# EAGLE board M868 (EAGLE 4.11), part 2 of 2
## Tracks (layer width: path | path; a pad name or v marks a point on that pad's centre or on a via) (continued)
N$55 (continued)
  Bottom 0.254: D10.C 38.73,139.07 40.01,139.07 D9.C
N$56
  Top 0.254: D6.A 40.64,41.91 38.73,43.82 38.73,50.17 D4.C
N$57
  Top 0.254: Q5.1 40.64,120.02 38.1,122.56 D10.A
N$58
  Top 0.254: Q3.1 45.72,74.3 44.45,75.57 44.45,124.46 40.64,128.27 D9.A
N$59
  Top 0.254: Q2.1 38.1,74.3 39.37,75.57 39.37,120.02 36.83,122.56 36.83,130.81 36.2,131.45 33.02,131.45 D9A.A
N$60
  Top 0.254: Q4.1 30.48,120.02 31.75,121.29 31.75,124.46 35.56,128.27 D7.A
N$61
  Bottom 0.254: E24.11 148.59,43.18 150.5,41.28 153.03,41.28 W2W1.2
N$62
  Bottom 0.254: E24.12 148.59,45.72 150.5,43.82 151.76,43.82 W4W3.2
N$63
  Top 0.254: D9A.C R39.2
  Bottom 0.254: D9A.C 33.66,139.07 34.92,139.07 D7.C
N$65
  Bottom 0.254: E20.3 158.75,45.72 156.84,47.63 155.57,47.63 W2W1.3
N$66  (via drill 0.61)
  Top 0.254: v68.58,53.34 68.58,40.64 E40.8 | v124.46,54.61 128.27,58.42 v128.27,116.84 | v150.5,180.34 133.35,163.2 v133.35,119.38
  Bottom 0.254: v68.58,53.34 104.14,53.34 105.41,54.61 v124.46,54.61 | v128.27,116.84 130.81,119.38 v133.35,119.38 E26.1 | v150.5,180.34 177.8,180.34 179.07,181.61 185.42,181.61 186.69,182.88 E19.12
N$67
  Bottom 0.254: E20.2 158.75,48.26 156.84,50.17 154.31,50.17 W4W3.3
N$68  (via drill 0.61)
  Top 0.254: v128.91,167.01 128.91,121.29 E30.13
  Bottom 0.254: v128.91,167.01 135.89,173.99 184.15,173.99 186.69,176.53 189.23,176.53 189.87,177.17 189.87,179.71 188.59,179.71 E19.11
N$69  (via drill 0.61)
  Top 0.254: v97.79,78.74 100.33,76.2 E33.11 | E44.2 15.24,50.8 15.24,83.82 E45.1 | v88.9,91.44 88.9,86.36 E33.2
  Bottom 0.254: v97.79,78.74 95.25,81.28 E33.2 | v88.9,91.44 60.33,91.44 59.05,92.71 20.32,92.71 13.97,86.36 E45.1
N$70  (via drill 0.61)
  Top 0.254: v29.21,78.74 29.21,46.99 19.05,46.99 18.41,47.63 18.41,48.9 E44.14 | v87,55.25 87,71.76 E33.3
  Bottom 0.254: v29.21,78.74 26.67,81.28 E45.14 | v87,55.25 46.99,55.25 44.45,52.71 23.5,52.71 21.59,50.8 E44.14
N$71
  Top 0.254: E44.13 22.23,50.17 22.23,62.87 18.41,66.68 18.41,81.92 E45.15
N$72
  Top 0.254: 58.42,144.78 58.42,114.3 E42.4 | 58.42,144.78 E43.3 | 58.42,144.78 58.42,175.9 57.15,177.17 R19.1
N$73
  Top 0.254: E43.4 53.98,146.69 53.98,150.5 E43.1 55.24,153.04 55.24,175.26 53.34,177.17 R21.1
  Bottom 0.254: E19.10 186.69,177.8 185.42,179.07 55.24,179.07 53.98,177.8 R21.1
N$74  (via drill 0.61)
  Top 0.254: E42.3 53.98,116.21 53.98,140.34 E43.5 53.34,144.78 53.34,160.02 v53.98,160.66 | v92.08,172.72 96.52,177.17 R20.1
  Bottom 0.254: v92.08,172.72 80.01,160.66 v53.98,160.66
N$77
  Top 0.254: E08.5 222.88,146.69 222.88,150.5 E08.2
N$78
  Top 0.254: R23.1 211.46,137.16 213.36,139.07 C37.1
  Bottom 0.254: C37.1 E08.7
N$79
  Top 0.254: C38.1 213.36,155.58 210.82,158.12 R24.1
  Bottom 0.254: E08.15 227.33,152.4 226.06,153.67 215.26,153.67 214,154.94 C38.1
N$80  (via drill 0.61)
  Top 0.254: v224.16,177.17 224.16,149.23 E08.12
  Bottom 0.254: E19.9 189.23,175.26 193.04,179.07 194.31,179.07 196.85,181.61 210.82,181.61 212.09,182.88 E09.3 214.63,182.88 216.53,180.98 220.34,180.98 E09.11 v224.16,177.17
N$81
  Bottom 0.254: C38.2 214,160.02 216.53,157.48 228.6,157.48 230.5,155.58 230.5,150.5 229.24,150.5 E08.14
N$82  (via drill 0.61)
  Top 0.254: v216.53,147.32 216.53,146.69 E08.6
  Bottom 0.254: v216.53,147.32 214,149.86 C37.2
N$83  (via drill 0.61)
  Top 0.254: v97.16,82.55 97.16,111.13 96.52,111.76 | E34.3 96.52,111.76 | 96.52,111.76 v96.52,111.13
  Bottom 0.254: v97.16,82.55 83.82,82.55 82.55,81.28 E37.13 | v96.52,111.13 99.69,111.13 100.33,111.76 E34.11 | 137.16,110.49 135.89,111.76 E30.11 123.83,112.4 120.02,112.4 118.11,114.3 E30.3 114.3,114.3 113.03,115.57 96.52,115.57 95.25,114.3 E34.3 | 137.16,110.49 138.43,109.22 E26.5 | 137.16,110.49 148.59,110.49 153.67,115.57 241.3,115.57 242.57,114.3 E03.3
N$84  (via drill 0.61)
  Top 0.254: R12.1 v132.08,110.49
  Bottom 0.254: 111.12,109.22 113.03,109.22 115.57,111.76 E30.4 120.65,111.76 123.19,109.22 E30.10 130.81,109.22 v132.08,110.49 | 111.12,109.22 E34.10 | 111.12,109.22 107.31,113.03 100.33,113.03 99.69,112.4 95.89,112.4 95.25,111.76 E34.4
N$85
  Top 0.254: E38.10 80.64,109.86 80.64,111.13 E38.11
N$86  (via drill 0.61)
  Top 0.254: E38.12 79.38,112.4 79.38,106.05 E38.8 81.92,103.51 81.92,91.44 v83.19,90.17
  Bottom 0.254: v83.19,90.17 146.69,90.17 147.96,88.9 248.28,88.9 248.28,74.3 E02.8
N$87  (via drill 0.61)
  Top 0.254: v22.86,49.53 27.94,54.61 v27.94,139.07
  Bottom 0.254: v22.86,49.53 17.78,49.53 13.97,45.72 E44.3 | E43.12 62.23,147.32 58.42,143.51 32.38,143.51 v27.94,139.07 27.3,138.43 24.77,138.43 24.13,139.07 20.32,139.07 20.32,137.8 21.59,136.53 36.2,136.53 43.18,129.54 72.39,129.54 73.66,130.81 260.35,130.81 260.35,120.65 252.73,113.03 246.38,113.03 245.11,111.76 E03.4
N$88  (via drill 0.61)
  Top 0.254: v138.43,94.62 141.6,97.79 141.6,109.86 E26.4
  Bottom 0.254: v138.43,94.62 5.71,94.62 5.71,106.68 9.53,110.49 17.78,110.49 19.05,111.76 E46.11
N$89  (via drill 0.61)
  Top 0.254: v121.92,95.89 108.58,95.89 v108.58,97.79
  Bottom 0.254: v121.92,95.89 143.51,95.89 149.86,89.54 248.92,89.54 248.92,78.74 E02.10 | v108.58,97.79 57.78,97.79 48.9,106.68 24.13,106.68 21.59,104.14 E46.8
N$90  (via drill 0.61)
  Top 0.254: E42.10 62.87,109.86 62.87,111.13 E42.11 60.96,114.3 60.96,127 | 60.96,127 R15.1 | v184.15,120.02 v184.15,127 184.15,143.51 E18.3 | v64.14,127 60.96,127
  Bottom 0.254: v184.15,120.02 186.06,118.11 241.3,118.11 242.57,116.84 E03.2 | v184.15,127 v64.14,127
N$92
  Top 0.254: 245.75,147.96 246.38,147.32 246.38,121.92 E03.1 | 245.75,147.96 E04.3 | 245.75,147.96 245.75,153.67 242.57,153.67 241.94,154.31 241.94,173.99 239.4,176.53 239.4,187.96 R42.2
N$94  (via drill 0.61)
  Top 0.254: v254.63,154.31 260.35,148.59 260.35,136.53 259.08,135.26 R17.1 | v237.49,168.28 234.95,168.28 C36.+
  Bottom 0.254: v254.63,154.31 252.73,152.4 E04.15 250.82,153.04 249.56,153.04 249.56,158.75 244.47,163.83 241.94,163.83 v237.49,168.28
N$95
  Bottom 0.254: E04.14 255.91,154.31 255.91,166.37 C36.-
N$96  (via drill 0.61)
  Top 0.254: v247.65,143.51 247.65,115.57 E03.11
  Bottom 0.254: v247.65,143.51 E04.4
N$97  (via drill 0.61)
  Top 0.254: v247.01,81.92 247.65,82.55 v247.65,114.3 | E03.13 250.82,116.21 250.82,114.94 E03.12
  Bottom 0.254: E02.4 v247.01,81.92 | v247.65,114.3 E03.12
N$98
  Bottom 0.254: E02.13 260.99,93.35 260.99,184.15 217.81,184.15 216.53,185.42 E09.2
N$100  (via drill 0.61)
  Top 0.254: v165.1,175.9 165.1,144.78 E23.6
  Bottom 0.254: v165.1,175.9 167,177.8 E19.5
N$101  (via drill 0.61)
  Top 0.254: v208.28,137.16 208.28,172.72 E09.5 | v173.99,134.62 168.91,139.7 E23.9
  Bottom 0.254: E27.9 148.59,139.7 149.86,140.97 165.1,140.97 166.37,139.7 E23.9 | v208.28,137.16 205.74,134.62 v173.99,134.62
N$102  (via drill 0.61)
  Top 0.254: v172.09,168.91 165.74,162.56 165.74,146.69 E23.11 | E09.12 222.88,180.98 222.88,174.63 E09.8
  Bottom 0.254: v172.09,168.91 173.35,170.18 217.17,170.18 219.71,172.72 E09.8
N$104  (via drill 0.61)
  Top 0.254: v173.35,182.88 173.35,153.04 E23.12
  Bottom 0.254: v173.35,182.88 175.9,185.42 E19.2
N$106
  Top 0.254: E23.8 165.74,139.07 165.74,142.88 166.37,143.51 173.99,143.51 173.99,181.61 E19.1
N$107  (via drill 0.61)
  Top 0.254: 156.21,192.41 200.03,192.41 200.03,189.23 | 156.21,192.41 91.44,192.41 76.2,177.17 76.2,144.78 E39.5 | 200.03,189.23 200.03,187.33 E14.2 | 156.21,192.41 v156.21,147.32 | 200.03,189.23 207.01,189.23 208.28,187.96 208.28,175.26 E14.8
  Bottom 0.254: v156.21,147.32 E23.3
N$108
  Top 0.254: R43.1 C39.1
  Bottom 0.254: E04.7 242.57,139.7 237.49,144.78 R43.1
N$109  (via drill 0.61)
  Top 0.254: v171.45,138.43 174.62,141.61 174.62,174.63 E19.4
  Bottom 0.254: v171.45,138.43 149.86,138.43 148.59,137.16 E27.8
N$110
  Bottom 0.254: E04.6 237.49,148.59 237.49,159.39 236.22,159.39 C39.2
N$111
  Top 0.254: R43.2 236.22,135.26 238.76,137.8 R26.2
N$112
  Bottom 0.254: R25.2 259.08,44.45 254,44.45 252.73,45.72 E01.12
ND0  (via drill 0.61)
  Top 0.254: v80.01,161.93 79.38,161.29 79.38,149.23 E39.12
  Bottom 0.254: v80.01,161.93 79.38,162.56 J1.FF
ND1  (via drill 0.61)
  Top 0.254: v67.94,163.83 67.94,150.5 E39.4
  Bottom 0.254: v67.94,163.83 62.87,168.91 27.3,168.91 26.67,168.28 26.67,165.74 27.94,165.74 J1.DD
ND2  (via drill 0.61)
  Top 0.254: v69.22,163.83 69.22,154.31 E39.2
  Bottom 0.254: v69.22,163.83 60.33,172.72 J1.X
POWER_OK\  (via drill 0.61)
  Top 0.254: v118.11,25.4 118.75,26.04 118.75,36.2 E28.6
  Bottom 0.254: v118.11,25.4 120.65,22.86 133.35,22.86 137.16,19.05 137.16,13.97 EDGE$.BV2
RD00  (via drill 0.61)
  Top 0.254: v182.25,191.14 182.25,172.09 175.26,165.1 175.26,116.84 176.53,116.84 177.8,118.11 181.61,118.11 182.88,116.84 182.88,81.28 E16.4
  Bottom 0.254: v182.25,191.14 181.61,190.5 85.72,190.5 84.45,189.23 | 84.45,189.23 83.19,187.96 R4.1 | 84.45,189.23 32.38,189.23 28.57,193.04 J1.D
RD01  (via drill 0.61)
  Top 0.254: v88.9,180.34 R5.1 | v192.41,154.31 192.41,134.62 195.58,131.45 195.58,81.28 E11.4
  Bottom 0.254: v88.9,180.34 83.82,185.42 43.81,185.42 | 43.81,185.42 J1.L | v192.41,154.31 187.96,158.75 108.58,158.75 91.44,175.9 53.34,175.9 43.81,185.42
RD02  (via drill 0.61)
  Top 0.254: v88.9,174.63 90.17,175.9 | 90.17,175.9 92.08,177.8 R7.1 | v210.82,78.74 208.91,80.65 v208.91,123.83 | v90.81,128.27 90.17,128.91 90.17,175.9
  Bottom 0.254: v88.9,174.63 88.27,175.26 J1.V | v208.91,123.83 204.47,128.27 v90.81,128.27 | v210.82,78.74 E06.4
RMT  (via drill 0.61)
  Top 0.254: R1.1 84.45,187.96 81.92,190.5 J1.F | v157.48,182.88 157.48,137.16 163.83,130.81 163.83,82.55 E21.4
  Bottom 0.254: v157.48,182.88 90.81,182.88 85.72,187.96 R1.1
RTT\
  Top 0.254: E42.6 48.9,113.67 48.9,166.37 38.1,177.17 R18.1 37.47,177.8 27.94,187.33 J1.J
RUN  (via drill 0.61)
  Top 0.254: v147.32,31.75 144.78,29.21 v144.78,17.15
  Bottom 0.254: v147.32,31.75 161.29,31.75 E20.9 | v144.78,17.15 141.6,13.97 EDGE$.BU2
S/G\
  Bottom 0.254: E46.13 19.05,116.84 17.78,118.11 9.53,118.11 6.35,121.29 6.35,158.75 26.04,158.75 27.3,160.02 J1.JJ
SEL_ECHO
  Top 0.254: 31.75,114.3 R34.2 | 31.75,114.3 R33.2 R32.2 | 31.75,114.3 31.75,78.11 35.56,74.3 Q2.2 | R31.2 R30.2 Q5.2 43.18,120.02 39.37,123.83 39.37,130.81 36.83,133.35 36.83,173.36 27.94,182.25 J1.N
  Bottom 0.254: R32.2 36.2,114.3 37.47,113.03 38.73,113.03 40.01,114.3 R31.2
SKIP\
  Top 0.254: E41.13 61.59,79.38 61.59,75.57 E41.10 61.59,71.76 61.59,34.93 82.55,13.97 EDGE$.CS1
  Bottom 0.254: E41.1 57.15,83.82 59.69,81.28 E41.13
SR00  (via drill 0.61)
  Top 0.254: 191.13,76.84 v191.13,138.43 | 191.13,76.84 E16.11 | v191.77,30.48 191.13,31.12 191.13,76.84
  Bottom 0.254: v191.13,138.43 194.94,142.24 E13.6 | v191.77,30.48 230.5,30.48 230.5,33.66 E05.10
SR01  (via drill 0.61)
  Top 0.254: v201.93,49.53 202.56,50.17 202.56,70.49 | 202.56,70.49 E11.11 | 202.56,70.49 202.56,135.26 E13.7
  Bottom 0.254: v201.93,49.53 226.06,49.53 227.33,48.26 E05.15
SR02  (via drill 0.61)
  Top 0.254: E05.6 222.88,40.01 222.88,54.61 225.43,57.15 225.43,70.49 E06.11 231.78,76.84 231.78,151.13 v226.69,151.13
  Bottom 0.254: v226.69,151.13 200.66,151.13 199.39,152.4 E13.2
SR03  (via drill 0.61)
  Top 0.254: v219.07,66.04 220.34,64.77 220.34,51.44 E05.1
  Bottom 0.254: v219.07,66.04 191.77,66.04 189.23,68.58 E16.9
SR04
  Top 0.254: E10.10 203.2,38.1 203.2,66.04 E11.9
SR05  (via drill 0.61)
  Top 0.254: v224.16,46.99 226.06,48.9 226.06,66.04 E06.9
  Bottom 0.254: v224.16,46.99 219.71,46.99 218.44,48.26 E10.15
SR06  (via drill 0.61)
  Top 0.254: v185.42,71.12 v185.42,39.37
  Bottom 0.254: v185.42,39.37 195.58,39.37 196.85,38.1 E10.6 | v185.42,71.12 E16.7
SR07
  Top 0.254: E10.1 197.49,51.44 197.49,66.68 196.22,67.95 196.22,69.22 E11.7
SR08  (via drill 0.61)
  Top 0.254: v189.87,64.77 189.87,37.47 E15.10
  Bottom 0.254: v189.87,64.77 219.71,64.77 222.88,67.95 222.88,70.49 221.62,70.49 E06.7
SR09  (via drill 0.61)
  Top 0.254: v182.88,52.07 182.88,56.52 182.25,57.15 182.25,74.3 E16.5
  Bottom 0.254: v182.88,52.07 186.69,48.26 E15.15
SR10  (via drill 0.61)
  Top 0.254: v175.9,75.57 175.9,38.1 E15.6
  Bottom 0.254: v175.9,75.57 176.53,74.93 195.58,74.93 196.85,76.2 E11.5
SR11  (via drill 0.61)
  Top 0.254: v179.71,59.06 179.71,51.44 E15.1
  Bottom 0.254: v179.71,59.06 180.34,59.69 234.31,59.69 235.59,60.96 235.59,74.93 223.52,74.93 222.25,76.2 E06.5
SYNC  (via drill 0.61)
  Top 0.254: 149.22,146.69 149.86,147.32 v149.86,161.93 | 149.22,146.69 E27.11 | v143.51,123.19 149.22,128.91 149.22,146.69
  Bottom 0.254: E42.5 53.98,111.13 53.98,116.84 E42.2 57.15,116.84 62.87,122.56 91.44,122.56 92.08,123.19 v143.51,123.19 | v149.86,161.93 155.57,167.64 212.09,167.64 214,169.55 220.34,169.55 222.88,172.09 222.88,174.63 221.62,174.63 E09.9
T/M_ENABLE  (via drill 0.61)
  Top 0.254: v15.24,144.15 15.24,114.3 E46.4
  Bottom 0.254: v15.24,144.15 24.77,153.67 26.04,153.67 27.3,154.94 J1.NN
TP3  (via drill 0.61)
  Top 0.254: v112.39,34.29 109.86,31.75 v109.86,15.24
  Bottom 0.254: v112.39,34.29 162.56,34.29 162.56,38.1 E20.11 | v109.86,15.24 109.86,13.97 EDGE$.CH2
TP4  (via drill 0.61)
  Top 0.254: v99.69,31.75 101.6,29.85 v101.6,17.15
  Bottom 0.254: v99.69,31.75 32.38,31.75 22.23,41.91 15.24,41.91 13.97,40.64 E44.5 | v101.6,17.15 104.78,13.97 EDGE$.CJ2
TPG0  (via drill 0.61)
  Top 0.254: v183.51,151.13 195.58,163.2 195.58,175.26 196.85,176.53 205.1,176.53 205.1,175.9 E14.9
  Bottom 0.254: v183.51,151.13 170.18,151.13 168.91,149.86 E23.13
UNITH  (via drill 0.61)
  Top 0.254: v85.09,156.85 85.09,152.4 83.82,151.13 83.82,144.78 E39.10
  Bottom 0.254: v85.09,156.85 83.82,158.12 63.5,158.12 62.87,158.75 29.84,158.75 28.57,157.48 J1.LL
VCC  (via drill 0.61)
  Top 0.635: R10.2 R20.2 R7.2 R5.2 88.9,187.33 86.36,184.79 86.36,179.71 85.09,178.44 R1.2 R4.2 82.55,177.17 81.92,176.53 81.92,153.04 E39.14 | C20.1 154.94,165.74 152.4,168.28 R22.1 152.4,178.44 151.76,179.07 151.76,185.42 149.86,187.33 R6.2 R12.2 C30.1 | R9.2 R8.2 R13.1 R14.1 R15.2 | R18.2 R21.2 R19.2 R15.2 | E43.14 62.23,153.67 C29.1 62.23,186.06 60.96,187.33 R15.2 | E04.16 250.19,156.21 C4.1 250.19,160.66 246.38,164.47 R26.3 | E08.16 226.06,157.48 C8.1 C9.1 226.06,168.28 231.14,173.36 R16.2 230.5,175.26 228.6,177.17 R42.1 228.6,180.34 E09.14 | E03.14 250.19,120.65 C3.1 | R24.2 R23.2 | C12.1 204.47,125.1 203.84,125.73 203.84,139.07 E13.5 | E18.14 189.87,150.5 189.87,128.27 186.69,125.1 C14.1 186.69,120.65 184.78,118.75 v184.78,105.41 | E42.14 62.23,120.65 C28.1 | E37.14 78.74,86.36 C24.1 78.11,99.06 78.11,116.21 E38.14 | E36.5 72.39,40.64 69.85,43.18 v69.85,50.8 69.85,69.85 68.58,71.12 C33.1 68.58,74.3 66.67,76.2 66.67,81.92 64.77,83.82 E41.14 62.23,85.09 C27.1 | E45.16 12.7,93.98 C32.1 12.7,99.7 17.14,104.14 17.14,116.21 E46.14 | R27.2 C43.1 35.56,56.52 36.83,57.79 36.83,66.68 37.47,67.31 39.37,67.31 39.37,65.41 40.01,64.77 44.45,64.77 44.45,70.49 47.62,73.66 47.62,80.01 C46.+ | E44.8 17.14,38.74 17.14,53.34 19.05,55.25 C31.1 | E33.14 100.33,85.09 C23.1 | C46.+ R11.2 50.8,88.27 53.34,90.81 C26.1 | v45.72,86.36 47.62,84.46 47.62,82.55 C46.+ | C2.1 254,65.41 251.46,62.87 C1.1 E01.14 257.81,44.45 257.81,20.96 C34.+ | E10.16 204.47,52.07 C10.1 | E05.16 227.33,52.07 C5.1 | 130.81,69.22 132.08,70.49 R2.2 | 130.81,69.22 130.81,32.39 129.54,31.12 C21.1 129.54,23.5 127.64,21.59 C35.+ 126.36,21.59 126.36,33.66 E28.8 126.36,37.47 126.36,51.44 125.73,52.07 121.92,52.07 C22.1 121.28,55.88 v118.75,53.34
  Top 0.635: E16.16 187.32,87 187.32,103.51 E17.8 | C11.1 204.47,90.81 205.1,90.17 205.1,87 E11.16 | E06.16 227.33,87.63 C6.1 227.33,100.33 v227.97,100.97 | C19.1 152.4,81.28 E25.16 145.41,84.46 145.41,55.88 C18.1 146.05,52.07 E24.14 | E15.16 186.69,52.07 C13.1 | E20.8 165.1,38.1 C16.1 165.1,83.82 E21.16 169.54,88.27 169.54,117.48 E22.14 | 130.81,69.22 v130.81,86.36
  Bottom 0.635: C30.1 108.58,187.96 107.31,189.23 102.23,189.23 100.97,187.96 R10.2 | 83.82,153.67 82.55,152.4 E39.14 | 83.82,153.67 C25.1 95.25,153.67 96.52,152.4 E35.14 102.87,152.4 104.14,153.67 121.92,153.67 | 121.92,153.67 123.19,152.4 E31.14 | 121.92,153.67 144.78,153.67 146.05,152.4 E27.14 | 83.82,153.67 66.04,153.67 64.77,152.4 E43.14 | R26.1 249.56,175.26 247.01,172.72 R26.3 245.75,172.72 240.66,177.8 R42.1 | 193.04,186.69 193.04,187.33 188.59,187.33 E19.14 | 193.04,186.69 C15.1 | 193.04,186.69 203.2,186.69 204.47,187.96 E14.14 207.01,187.96 208.28,189.23 218.44,189.23 219.71,187.96 E09.14 | R17.2 C3.1 249.56,124.46 248.28,125.73 229.24,125.73 227.97,124.46 C7.1 226.69,124.46 224.79,122.56 207.01,122.56 205.1,124.46 C12.1 203.84,124.46 202.56,123.19 198.75,123.19 198.12,123.83 187.96,123.83 187.32,124.46 C14.1 | E23.14 168.91,152.4 170.18,153.67 185.42,153.67 186.69,152.4 E18.14 | E13.5 199.39,144.78 200.66,146.05 208.91,146.05 210.19,147.32 R23.2 | E08.16 227.33,154.94 226.06,156.21 212.72,156.21 211.46,154.94 R24.2 210.19,154.94 205.1,160.02 160.66,160.02 155.57,165.1 C20.1 | 99.06,120.65 100.33,119.38 E34.14 | 83.82,120.65 99.06,120.65 | 83.82,120.65 82.55,119.38 E38.14 | 99.06,120.65 121.92,120.65 123.19,119.38 E30.14 | 83.82,120.65 66.04,120.65 64.77,119.38 E42.14 | v69.85,50.8 E40.14 | C43.1 34.92,55.88 33.66,54.61 20.95,54.61 19.68,55.88 C31.1 | E33.14 102.87,83.82 104.14,85.09 121.92,85.09 123.19,86.36 E29.16 v130.81,86.36 | C26.1 59.05,91.44 61.59,88.9 C27.1 62.87,88.9 64.14,87.63 95.89,87.63 97.16,88.9 C23.1 | v45.72,86.36 E45.16 | E37.14 80.01,83.82 78.74,82.55 66.04,82.55 64.77,83.82 E41.14
  Bottom 0.635: C10.1 205.1,55.88 206.38,54.61 225.43,54.61 226.69,55.88 C5.1 | E01.14 250.19,50.8 248.92,52.07 231.14,52.07 229.87,50.8 E05.16 | EDGE$.AA2 260.35,13.97 259.71,13.97 259.71,19.05 C34.+ 257.81,20.96 255.91,22.86 234.95,22.86 232.41,20.32 191.77,20.32 191.77,13.97 EDGE$.BA2 | EDGE$.CA2 127,13.97 C35.+ | E12.8 204.47,104.14 203.2,105.41 190.5,105.41 189.23,104.14 E17.8 186.06,104.14 v184.78,105.41 | 208.28,85.09 207.01,86.36 E11.16 | 208.28,85.09 209.55,83.82 R3.2 214,83.82 215.26,85.09 226.06,85.09 227.33,86.36 E06.16 | v227.97,100.97 227.97,103.51 E07.8 | E02.14 250.82,87 250.82,90.81 227.33,90.81 C6.1 | 208.28,85.09 190.5,85.09 189.23,86.36 E16.16 186.69,86.36 185.42,85.09 177.8,85.09 176.53,86.36 E21.16 | E26.14 148.59,119.38 149.86,120.65 165.1,120.65 166.37,119.38 E22.14 C17.1 | v118.75,53.34 105.41,53.34 102.87,50.8 E32.14 | 163.19,54.61 164.47,55.88 C16.1 | 163.19,54.61 152.4,54.61 148.59,50.8 E24.14 | 163.19,54.61 184.78,54.61 186.06,55.88 C13.1 | C22.1 139.06,55.88 140.34,54.61 144.15,54.61 145.41,55.88 C18.1 | E10.16 200.66,50.8 199.39,52.07 190.5,52.07 189.23,50.8 E15.16
WD_ENAB
  Top 0.254: E46.10 22.86,111.76 22.86,142.88 26.04,146.05 29.21,146.05 29.21,168.28 27.94,169.55 J1.Z
WPT  (via drill 0.61)
  Top 0.254: v66.67,163.83 66.67,146.69 E39.6
  Bottom 0.254: v66.67,163.83 62.87,167.64 J1.BB
WRT_ECHO  (via drill 0.61)
  Top 0.254: v24.13,176.53 8.89,161.29 8.89,67.95 7.62,66.68 C47.1
  Bottom 0.254: C47.1 8.26,66.04 9.53,67.31 41.27,67.31 42.55,66.04 R48.1 | v24.13,176.53 26.04,176.53 27.3,177.8 J1.T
